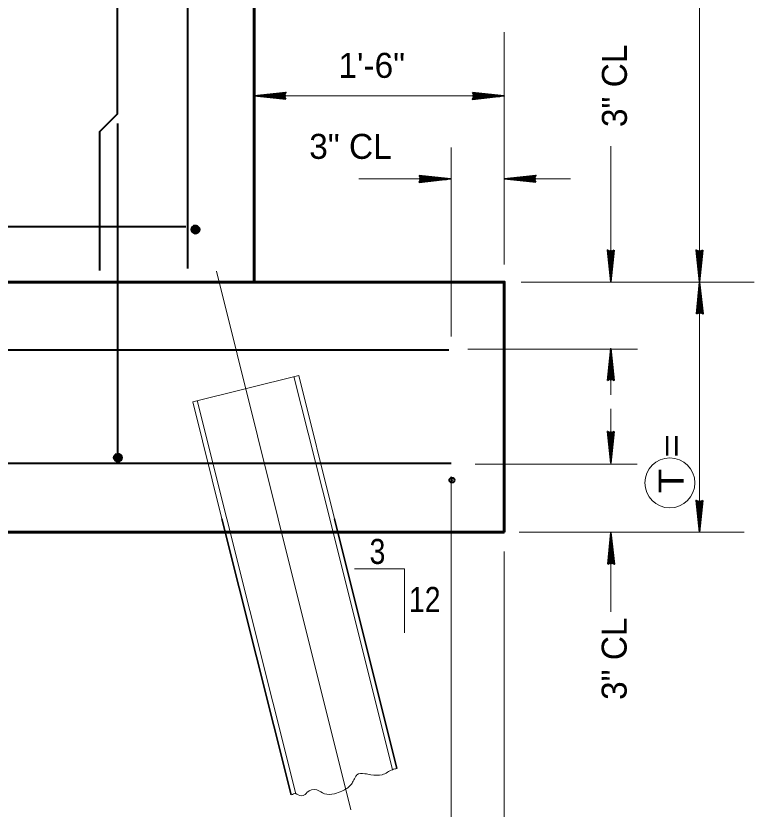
# Model space of a CAD drawing. Extents: x 3.64 to 6.84, y -0.8 to 1.19.
# Drawn here: x 4.5316 to 4.7778, y -0.2344 to 0.03 of the extents above; entities that cross this region are included whole.
import ezdxf
from ezdxf.enums import TextEntityAlignment as Align

# ---------------------------------------------------------------- set-up
doc = ezdxf.new("R2010")
doc.units = 0
doc.header["$LTSCALE"] = 0.0033
doc.header["$PDMODE"] = 32
doc.header["$PDSIZE"] = 0.00165
doc.linetypes.add('DOT_DASHED', pattern=[7.7, 5, -1.2, 0.3, -1.2])
doc.linetypes.add('MEDIUM_DASHED', pattern=[4.5, 3, -1.5])
doc.layers.add('1', color=7, linetype='Continuous', lineweight=40)
doc.layers.add('5', color=7, linetype='MEDIUM_DASHED', lineweight=13)

msp = doc.modelspace()

# ---------------------------------------------------------------- linework, layer by layer
at = {"layer": '1', "lineweight": 13}
for p, q in [((4.759583, 0.27275), (4.759583, -0.142083)), ((4.694417, -0.052833), (4.694417, 0.024583)), ((4.611083, 0.003333), (4.694, 0.003333)), ((4.67675, -0.076833), (4.67675, -0.013917)), ((4.73, -0.04875), (4.73, -0.013417)), ((4.645917, -0.024333), (4.66675, -0.024333)), ((4.704333, -0.024333), (4.7165, -0.024333)), ((4.700083, -0.05875), (4.77775, -0.05875)), ((4.682333, -0.081083), (4.738917, -0.081083)), ((4.729917, -0.096333), (4.729917, -0.086417)), ((4.73, -0.110833), (4.73, -0.101)), ((4.68475, -0.119417), (4.73875, -0.119417)), ((4.67675, -0.123583), (4.67675, -0.36975)), ((4.67675, -0.13175), (4.67675, -0.133333)), ((4.694417, -0.142083), (4.694417, -0.142417)), ((4.699417, -0.142083), (4.774417, -0.142083)), ((4.694417, -0.148583), (4.694417, -0.230333)), ((4.73, -0.168583), (4.73, -0.152083)), ((4.6445, -0.15425), (4.661167, -0.15425)), ((4.661167, -0.15425), (4.661167, -0.175583)), ((4.694417, -0.22875), (4.694417, -0.413667))]:
    msp.add_line(p, q, dxfattribs=at)
at = {"layer": '1'}
for p, q in [((4.588833, 0.253083), (4.588833, -0.05425)), ((4.5655, -0.005917), (4.5655, -0.11825)), ((4.471167, -0.040167), (4.588333, -0.040167)), ((4.590333, -0.041833), (4.592333, -0.042167)), ((4.590417, -0.041333), (4.592417, -0.04175)), ((4.590417, -0.041583), (4.592417, -0.041917)), ((4.590417, -0.041667), (4.592333, -0.042)), ((4.590417, -0.04175), (4.592333, -0.042083)), ((4.590583, -0.040417), (4.5905, -0.041917)), ((4.5905, -0.040917), (4.5925, -0.04125)), ((4.5905, -0.041), (4.5925, -0.041417)), ((4.5905, -0.041083), (4.592417, -0.0415)), ((4.5905, -0.041167), (4.592417, -0.041583)), ((4.590667, -0.040417), (4.590583, -0.041917)), ((4.590583, -0.040417), (4.592583, -0.04075)), ((4.590583, -0.0405), (4.592583, -0.040833)), ((4.590583, -0.040583), (4.592583, -0.041)), ((4.590583, -0.040667), (4.592583, -0.041083)), ((4.590583, -0.040833), (4.5925, -0.041167)), ((4.590667, -0.04025), (4.592583, -0.040583)), ((4.59075, -0.040417), (4.590667, -0.041917)), ((4.590833, -0.040417), (4.59075, -0.041917)), ((4.590917, -0.040417), (4.590833, -0.041917)), ((4.591083, -0.040417), (4.591, -0.041917)), ((4.591167, -0.040417), (4.591083, -0.041917)), ((4.59125, -0.040417), (4.591167, -0.041917)), ((4.591333, -0.040417), (4.59125, -0.041917)), ((4.591417, -0.040417), (4.591333, -0.041917)), ((4.5915, -0.040417), (4.591417, -0.041917)), ((4.591583, -0.040417), (4.5915, -0.041917)), ((4.59175, -0.0405), (4.591583, -0.042)), ((4.591917, -0.0405), (4.59175, -0.042)), ((4.592, -0.0405), (4.591917, -0.042)), ((4.592, -0.0405), (4.591917, -0.042)), ((4.592083, -0.0405), (4.592, -0.042)), ((4.592167, -0.0405), (4.592083, -0.042)), ((4.59225, -0.0405), (4.592167, -0.042)), ((4.592333, -0.0405), (4.59225, -0.042)), ((4.592417, -0.0405), (4.592333, -0.042)), ((4.5925, -0.0405), (4.592417, -0.042)), ((4.592667, -0.0405), (4.592583, -0.042)), ((4.565, -0.116083), (4.564667, -0.118083)), ((4.565083, -0.116167), (4.56475, -0.118083)), ((4.565167, -0.116167), (4.564833, -0.118083)), ((4.56525, -0.116167), (4.564917, -0.118167)), ((4.566417, -0.116333), (4.564917, -0.11625)), ((4.5655, -0.116167), (4.565083, -0.118167)), ((4.565667, -0.11625), (4.56525, -0.118167)), ((4.56575, -0.11625), (4.565333, -0.118167)), ((4.565833, -0.11625), (4.565417, -0.11825)), ((4.565917, -0.11625), (4.565583, -0.11825)), ((4.566333, -0.1175), (4.564833, -0.117333)), ((4.566333, -0.117667), (4.564833, -0.1175)), ((4.566333, -0.11775), (4.564833, -0.117667)), ((4.566333, -0.11775), (4.564833, -0.117667)), ((4.566333, -0.117833), (4.564833, -0.11775)), ((4.566333, -0.117917), (4.564833, -0.117833)), ((4.566333, -0.118), (4.564833, -0.117917)), ((4.566333, -0.118083), (4.564833, -0.118)), ((4.566333, -0.118167), (4.564833, -0.118083)), ((4.566333, -0.11825), (4.564833, -0.118167)), ((4.566333, -0.118417), (4.564833, -0.118333)), ((4.566417, -0.116417), (4.564917, -0.116333)), ((4.566417, -0.1165), (4.564917, -0.116417)), ((4.566417, -0.116583), (4.564917, -0.1165)), ((4.566417, -0.116667), (4.564917, -0.116583)), ((4.566417, -0.116833), (4.564917, -0.11675)), ((4.566417, -0.116917), (4.564917, -0.116833)), ((4.566417, -0.117), (4.564917, -0.116917)), ((4.566417, -0.117083), (4.564917, -0.117)), ((4.566417, -0.117167), (4.564917, -0.117083)), ((4.566417, -0.11725), (4.564917, -0.117167)), ((4.566417, -0.117333), (4.564917, -0.11725)), ((4.566, -0.116333), (4.565667, -0.11825)), ((4.566167, -0.116333), (4.56575, -0.118333)), ((4.56625, -0.116333), (4.565833, -0.118333)), ((4.566333, -0.116333), (4.566, -0.118333)), ((4.566417, -0.116333), (4.566083, -0.118333)), ((4.566583, -0.116417), (4.56625, -0.118333))]:
    msp.add_line(p, q, dxfattribs=at)
at = {"layer": '1', "lineweight": 35}
for p, q in [((4.621667, 0.003333), (4.611083, 0.003333)), ((4.621417, 0.0025), (4.613583, 0.0035)), ((4.621417, 0.0025), (4.613583, 0.003333)), ((4.621417, 0.002333), (4.613583, 0.00325)), ((4.621417, 0.002333), (4.613583, 0.00325)), ((4.621417, 0.002417), (4.613583, 0.00325)), ((4.621417, 0.004417), (4.614083, 0.003583)), ((4.621417, 0.00425), (4.614083, 0.0035)), ((4.621417, 0.004167), (4.614083, 0.003333)), ((4.6215, 0.004), (4.614167, 0.00325)), ((4.683833, 0.003333), (4.694417, 0.003333)), ((4.684, 0.002667), (4.691333, 0.003417)), ((4.684083, 0.004333), (4.691917, 0.003417)), ((4.684083, 0.004333), (4.691917, 0.003417)), ((4.684083, 0.00425), (4.691917, 0.003417)), ((4.684083, 0.004167), (4.691917, 0.003333)), ((4.684083, 0.004167), (4.691917, 0.003167)), ((4.684083, 0.0025), (4.691417, 0.003333)), ((4.684083, 0.002417), (4.691417, 0.003167)), ((4.684083, 0.00225), (4.691417, 0.003083)), ((4.666333, -0.023333), (4.674167, -0.02425)), ((4.666333, -0.023333), (4.674167, -0.02425)), ((4.666333, -0.023417), (4.674167, -0.02425)), ((4.666333, -0.0235), (4.674167, -0.024333)), ((4.666333, -0.0235), (4.674167, -0.0245)), ((4.70475, -0.02325), (4.697417, -0.024083)), ((4.70475, -0.023417), (4.697417, -0.024167)), ((4.70475, -0.0235), (4.697417, -0.024333)), ((4.704833, -0.023667), (4.6975, -0.024417)), ((4.666083, -0.024333), (4.676667, -0.024333)), ((4.66625, -0.025), (4.673583, -0.02425)), ((4.666333, -0.025167), (4.673667, -0.024333)), ((4.666333, -0.02525), (4.673667, -0.0245)), ((4.666333, -0.025417), (4.673667, -0.024583)), ((4.705, -0.024333), (4.694417, -0.024333)), ((4.70475, -0.025167), (4.696917, -0.024167)), ((4.70475, -0.025167), (4.696917, -0.024333)), ((4.70475, -0.025333), (4.696917, -0.024417)), ((4.70475, -0.025333), (4.696917, -0.024417)), ((4.70475, -0.02525), (4.696917, -0.024417)), ((4.728917, -0.048333), (4.72975, -0.055667)), ((4.729083, -0.048333), (4.729833, -0.055667)), ((4.729167, -0.048333), (4.73, -0.055667)), ((4.729333, -0.04825), (4.730083, -0.055583)), ((4.730833, -0.048333), (4.729833, -0.056167)), ((4.73, -0.048083), (4.73, -0.058667)), ((4.730833, -0.048333), (4.73, -0.056167)), ((4.731, -0.048333), (4.730083, -0.056167)), ((4.731, -0.048333), (4.730083, -0.056167)), ((4.730917, -0.048333), (4.730083, -0.056167)), ((4.7585, -0.048333), (4.759333, -0.055667)), ((4.758667, -0.048333), (4.759417, -0.055667)), ((4.75875, -0.048333), (4.759583, -0.055667)), ((4.758917, -0.04825), (4.759667, -0.055583)), ((4.760417, -0.048333), (4.759417, -0.056167)), ((4.759583, -0.048083), (4.759583, -0.058667)), ((4.760417, -0.048333), (4.759583, -0.056167)), ((4.760583, -0.048333), (4.759667, -0.056167)), ((4.760583, -0.048333), (4.759667, -0.056167)), ((4.7605, -0.048333), (4.759667, -0.056167)), ((4.759583, -0.069333), (4.759583, -0.05875)), ((4.758583, -0.069083), (4.7595, -0.06125)), ((4.758583, -0.069083), (4.7595, -0.06125)), ((4.758667, -0.069083), (4.7595, -0.06125)), ((4.75875, -0.069083), (4.759583, -0.06125)), ((4.75875, -0.069083), (4.75975, -0.06125)), ((4.76025, -0.069167), (4.7595, -0.061833)), ((4.760417, -0.069083), (4.759583, -0.06175)), ((4.7605, -0.069083), (4.75975, -0.06175)), ((4.760667, -0.069083), (4.759833, -0.06175)), ((4.729917, -0.0915), (4.729917, -0.080917)), ((4.728917, -0.09125), (4.729833, -0.083417)), ((4.728917, -0.09125), (4.729833, -0.083417)), ((4.729, -0.09125), (4.729833, -0.083417)), ((4.729083, -0.09125), (4.729917, -0.083417)), ((4.729083, -0.09125), (4.730083, -0.083417)), ((4.730583, -0.091333), (4.729833, -0.084)), ((4.73075, -0.09125), (4.729917, -0.083917)), ((4.730833, -0.09125), (4.730083, -0.083917)), ((4.731, -0.09125), (4.730167, -0.083917)), ((4.728917, -0.10875), (4.72975, -0.116083)), ((4.729083, -0.10875), (4.729833, -0.116083)), ((4.729167, -0.10875), (4.73, -0.116083)), ((4.729333, -0.108667), (4.730083, -0.116)), ((4.730833, -0.10875), (4.729833, -0.116583)), ((4.73, -0.1085), (4.73, -0.119083)), ((4.730833, -0.10875), (4.73, -0.116583)), ((4.731, -0.10875), (4.730083, -0.116583)), ((4.731, -0.10875), (4.730083, -0.116583)), ((4.730917, -0.10875), (4.730083, -0.116583)), ((4.7585, -0.13175), (4.759333, -0.139083)), ((4.758667, -0.13175), (4.759417, -0.139083)), ((4.75875, -0.13175), (4.759583, -0.139083)), ((4.758917, -0.131667), (4.759667, -0.139)), ((4.760417, -0.13175), (4.759417, -0.139583)), ((4.759583, -0.1315), (4.759583, -0.142083)), ((4.760417, -0.13175), (4.759583, -0.139583)), ((4.760583, -0.13175), (4.759667, -0.139583)), ((4.760583, -0.13175), (4.759667, -0.139583)), ((4.7605, -0.13175), (4.759667, -0.139583)), ((4.73, -0.15275), (4.73, -0.142167)), ((4.729, -0.1525), (4.729917, -0.144667)), ((4.729, -0.1525), (4.729917, -0.144667)), ((4.729083, -0.1525), (4.729917, -0.144667)), ((4.729167, -0.1525), (4.73, -0.144667)), ((4.729167, -0.1525), (4.730167, -0.144667)), ((4.730667, -0.152583), (4.729917, -0.14525)), ((4.730833, -0.1525), (4.73, -0.145167)), ((4.730917, -0.1525), (4.730167, -0.145167)), ((4.731083, -0.1525), (4.73025, -0.145167))]:
    msp.add_line(p, q, dxfattribs=at)
at = {"layer": '1', "lineweight": 60}
msp.add_line((4.694417, -0.142083), (3.944417, -0.142083), dxfattribs=at)
for points in [[(4.611083, 0.274583), (4.611083, -0.05875), (4.694417, -0.05875), (4.694417, -0.142083)], [(4.02775, -0.05875), (4.270917, -0.05875), (4.611083, -0.05875)]]:
    msp.add_lwpolyline(points, dxfattribs=at)
at = {"layer": '1'}
for points in [[(4.565417, 0.253583), (4.565417, -0.00275), (4.5595, -0.008667), (4.5595, -0.054917)], [(4.590167, -0.04125), (4.59275, -0.040917), (4.590417, -0.040417), (4.59275, -0.0415), (4.590333, -0.041917), (4.592333, -0.04225), (4.592333, -0.040167), (4.591417, -0.0425), (4.591667, -0.039917), (4.590667, -0.04225), (4.591, -0.039917), (4.591833, -0.0425), (4.59025, -0.04075), (4.592667, -0.040583), (4.591, -0.042417), (4.592083, -0.04), (4.590417, -0.040417), (4.590333, -0.041917), (4.591417, -0.0425), (4.592333, -0.04225), (4.59275, -0.0415), (4.592667, -0.040583), (4.592083, -0.04), (4.591417, -0.041083), (4.592583, -0.042), (4.590667, -0.04225), (4.591417, -0.041083), (4.590333, -0.040583), (4.591333, -0.039917), (4.591417, -0.041), (4.59225, -0.04225), (4.59025, -0.041), (4.591583, -0.040667), (4.592333, -0.040167)], [(4.270917, -0.077167), (4.33325, -0.077167), (4.3405, -0.081333), (4.675917, -0.081333)], [(4.271, -0.114917), (4.332583, -0.114917), (4.339833, -0.119083), (4.67675, -0.119083)], [(4.565583, -0.115917), (4.565917, -0.1185), (4.566417, -0.116167), (4.565333, -0.1185), (4.564917, -0.116083), (4.564583, -0.118083), (4.566667, -0.118083), (4.564333, -0.117167), (4.566917, -0.117417), (4.564583, -0.116417), (4.566917, -0.11675), (4.564333, -0.117583), (4.566083, -0.116), (4.56625, -0.118417), (4.564417, -0.11675), (4.566833, -0.117833), (4.566417, -0.116167), (4.564917, -0.116083), (4.564333, -0.117167), (4.564583, -0.118083), (4.565333, -0.1185), (4.56625, -0.118417), (4.566833, -0.117833), (4.56575, -0.117167), (4.564833, -0.118333), (4.564583, -0.116417), (4.56575, -0.117167), (4.56625, -0.116083), (4.566917, -0.117083), (4.565833, -0.117167), (4.564583, -0.118), (4.565833, -0.116), (4.566167, -0.117333), (4.566667, -0.118083)]]:
    msp.add_lwpolyline(points, dxfattribs=at)
at = {"layer": '1', "lineweight": 35}
for points in [[(4.621667, 0.00225), (4.611083, 0.003333), (4.621667, 0.0045), (4.621083, 0.003333)], [(4.620917, 0.00325), (4.61625, 0.003167), (4.61625, 0.00325), (4.617167, 0.00325), (4.620917, 0.003167), (4.617917, 0.003083), (4.621083, 0.003), (4.618833, 0.002917), (4.621083, 0.002833), (4.617583, 0.003083), (4.612917, 0.00325), (4.613833, 0.0035), (4.612583, 0.0035), (4.620917, 0.0035), (4.6185, 0.003667), (4.621083, 0.003667), (4.61575, 0.00325), (4.621083, 0.003917)], [(4.683833, 0.004417), (4.694417, 0.003333), (4.683833, 0.002167), (4.684417, 0.003333)], [(4.684583, 0.003417), (4.68925, 0.0035), (4.68925, 0.003417), (4.688333, 0.003417), (4.684583, 0.0035), (4.687583, 0.003583), (4.684417, 0.003667), (4.686667, 0.00375), (4.684417, 0.003833), (4.687917, 0.003583), (4.692583, 0.003417), (4.691667, 0.003167), (4.692917, 0.003167), (4.684583, 0.003167), (4.687, 0.003), (4.684417, 0.003), (4.68975, 0.003417), (4.684417, 0.00275)], [(4.666083, -0.02325), (4.676667, -0.024333), (4.666083, -0.0255), (4.666667, -0.024333)], [(4.705, -0.025417), (4.694417, -0.024333), (4.705, -0.023167), (4.704417, -0.024333)], [(4.70425, -0.024417), (4.699583, -0.0245), (4.699583, -0.024417), (4.7005, -0.024417), (4.70425, -0.0245), (4.70125, -0.024583), (4.704417, -0.024667), (4.702167, -0.02475), (4.704417, -0.024833), (4.700917, -0.024583), (4.69625, -0.024417), (4.697167, -0.024167), (4.695917, -0.024167), (4.70425, -0.024167), (4.701833, -0.024), (4.704417, -0.024), (4.699083, -0.024417), (4.704417, -0.02375)], [(4.666833, -0.02425), (4.6715, -0.024167), (4.6715, -0.02425), (4.670583, -0.02425), (4.666833, -0.024167), (4.669833, -0.024083), (4.666667, -0.024), (4.668917, -0.023917), (4.666667, -0.023833), (4.670167, -0.024083), (4.674833, -0.02425), (4.673917, -0.0245), (4.675167, -0.0245), (4.666833, -0.0245), (4.66925, -0.024667), (4.666667, -0.024667), (4.672, -0.02425), (4.666667, -0.024917)], [(4.731083, -0.048083), (4.73, -0.058667), (4.728833, -0.048083), (4.73, -0.048667)], [(4.730083, -0.048833), (4.730167, -0.0535), (4.730083, -0.0535), (4.730083, -0.052583), (4.730167, -0.048833), (4.73025, -0.051833), (4.730333, -0.048667), (4.730417, -0.050917), (4.7305, -0.048667), (4.73025, -0.052167), (4.730083, -0.056833), (4.729833, -0.055917), (4.729833, -0.057167), (4.729833, -0.048833), (4.729667, -0.05125), (4.729667, -0.048667), (4.730083, -0.054), (4.729417, -0.048667)], [(4.760667, -0.048083), (4.759583, -0.058667), (4.758417, -0.048083), (4.759583, -0.048667)], [(4.759667, -0.048833), (4.75975, -0.0535), (4.759667, -0.0535), (4.759667, -0.052583), (4.75975, -0.048833), (4.759833, -0.051833), (4.759917, -0.048667), (4.76, -0.050917), (4.760083, -0.048667), (4.759833, -0.052167), (4.759667, -0.056833), (4.759417, -0.055917), (4.759417, -0.057167), (4.759417, -0.048833), (4.75925, -0.05125), (4.75925, -0.048667), (4.759667, -0.054), (4.759, -0.048667)], [(4.7585, -0.069333), (4.759583, -0.05875), (4.76075, -0.069333), (4.759583, -0.06875)], [(4.7595, -0.068583), (4.759417, -0.063917), (4.7595, -0.063917), (4.7595, -0.064833), (4.759417, -0.068583), (4.759333, -0.065583), (4.75925, -0.06875), (4.759167, -0.0665), (4.759083, -0.06875), (4.759333, -0.06525), (4.7595, -0.060583), (4.75975, -0.0615), (4.75975, -0.06025), (4.75975, -0.068583), (4.759917, -0.066167), (4.759917, -0.06875), (4.7595, -0.063417), (4.760167, -0.06875)], [(4.728833, -0.0915), (4.729917, -0.080917), (4.731083, -0.0915), (4.729917, -0.090917)], [(4.729833, -0.09075), (4.72975, -0.086083), (4.729833, -0.086083), (4.729833, -0.087), (4.72975, -0.09075), (4.729667, -0.08775), (4.729583, -0.090917), (4.7295, -0.088667), (4.729417, -0.090917), (4.729667, -0.087417), (4.729833, -0.08275), (4.730083, -0.083667), (4.730083, -0.082417), (4.730083, -0.09075), (4.73025, -0.088333), (4.73025, -0.090917), (4.729833, -0.085583), (4.7305, -0.090917)], [(4.731083, -0.1085), (4.73, -0.119083), (4.728833, -0.1085), (4.73, -0.109083)], [(4.730083, -0.10925), (4.730167, -0.113917), (4.730083, -0.113917), (4.730083, -0.113), (4.730167, -0.10925), (4.73025, -0.11225), (4.730333, -0.109083), (4.730417, -0.111333), (4.7305, -0.109083), (4.73025, -0.112583), (4.730083, -0.11725), (4.729833, -0.116333), (4.729833, -0.117583), (4.729833, -0.10925), (4.729667, -0.111667), (4.729667, -0.109083), (4.730083, -0.114417), (4.729417, -0.109083)], [(4.760667, -0.1315), (4.759583, -0.142083), (4.758417, -0.1315), (4.759583, -0.132083)], [(4.759667, -0.13225), (4.75975, -0.136917), (4.759667, -0.136917), (4.759667, -0.136), (4.75975, -0.13225), (4.759833, -0.13525), (4.759917, -0.132083), (4.76, -0.134333), (4.760083, -0.132083), (4.759833, -0.135583), (4.759667, -0.14025), (4.759417, -0.139333), (4.759417, -0.140583), (4.759417, -0.13225), (4.75925, -0.134667), (4.75925, -0.132083), (4.759667, -0.137417), (4.759, -0.132083)], [(4.728917, -0.15275), (4.73, -0.142167), (4.731167, -0.15275), (4.73, -0.152167)], [(4.729917, -0.152), (4.729833, -0.147333), (4.729917, -0.147333), (4.729917, -0.14825), (4.729833, -0.152), (4.72975, -0.149), (4.729667, -0.152167), (4.729583, -0.149917), (4.7295, -0.152167), (4.72975, -0.148667), (4.729917, -0.144), (4.730167, -0.144917), (4.730167, -0.143667), (4.730167, -0.152), (4.730333, -0.149583), (4.730333, -0.152167), (4.729917, -0.146833), (4.730583, -0.152167)]]:
    msp.add_lwpolyline(points, close=True, dxfattribs=at)
for points in [[(4.620917, 0.00325), (4.621333, 0.0025), (4.621083, 0.00275), (4.620917, 0.003083), (4.620667, 0.003), (4.620833, 0.002667), (4.621, 0.003417), (4.621167, 0.003917), (4.621417, 0.004333)], [(4.684583, 0.003417), (4.684167, 0.004167), (4.684417, 0.003917), (4.684583, 0.003583), (4.684833, 0.003667), (4.684667, 0.004), (4.6845, 0.00325), (4.684333, 0.00275), (4.684083, 0.002333)], [(4.666833, -0.02425), (4.666417, -0.0235), (4.666667, -0.02375), (4.666833, -0.024083), (4.667083, -0.024), (4.666917, -0.023667), (4.66675, -0.024417), (4.666583, -0.024917), (4.666333, -0.025333)], [(4.70425, -0.024417), (4.704667, -0.025167), (4.704417, -0.024917), (4.70425, -0.024583), (4.704, -0.024667), (4.704167, -0.025), (4.704333, -0.02425), (4.7045, -0.02375), (4.70475, -0.023333)], [(4.730083, -0.048833), (4.730833, -0.048417), (4.730583, -0.048667), (4.73025, -0.048833), (4.730333, -0.049083), (4.730667, -0.048917), (4.729917, -0.04875), (4.729417, -0.048583), (4.729, -0.048333)], [(4.759667, -0.048833), (4.760417, -0.048417), (4.760167, -0.048667), (4.759833, -0.048833), (4.759917, -0.049083), (4.76025, -0.048917), (4.7595, -0.04875), (4.759, -0.048583), (4.758583, -0.048333)], [(4.7595, -0.068583), (4.75875, -0.069), (4.759, -0.06875), (4.759333, -0.068583), (4.75925, -0.068333), (4.758917, -0.0685), (4.759667, -0.068667), (4.760167, -0.068833), (4.760583, -0.069083)], [(4.729833, -0.09075), (4.729083, -0.091167), (4.729333, -0.090917), (4.729667, -0.09075), (4.729583, -0.0905), (4.72925, -0.090667), (4.73, -0.090833), (4.7305, -0.091), (4.730917, -0.09125)], [(4.730083, -0.10925), (4.730833, -0.108833), (4.730583, -0.109083), (4.73025, -0.10925), (4.730333, -0.1095), (4.730667, -0.109333), (4.729917, -0.109167), (4.729417, -0.109), (4.729, -0.10875)], [(4.759667, -0.13225), (4.760417, -0.131833), (4.760167, -0.132083), (4.759833, -0.13225), (4.759917, -0.1325), (4.76025, -0.132333), (4.7595, -0.132167), (4.759, -0.132), (4.758583, -0.13175)], [(4.729917, -0.152), (4.729167, -0.152417), (4.729417, -0.152167), (4.72975, -0.152), (4.729667, -0.15175), (4.729333, -0.151917), (4.730083, -0.152083), (4.730583, -0.15225), (4.731, -0.1525)]]:
    msp.add_lwpolyline(points, dxfattribs=at)
at = {"layer": '1'}
for centre in [(4.5915, -0.0412), (4.565633, -0.11725)]:
    msp.add_circle(centre, 0.00132, dxfattribs=at)
at = {"layer": '1', "lineweight": 13}
msp.add_circle((4.749667, -0.125667), 0.008333, dxfattribs=at)
at = {"layer": '1'}
msp.add_point((4.677, -0.12475), dxfattribs=at)
at = {"layer": '5'}
for p, q in [((4.625917, -0.089917), (4.590583, -0.098667)), ((4.624333, -0.09025), (4.63625, -0.137667)), ((4.625917, -0.089917), (4.637833, -0.137667)), ((4.590583, -0.098667), (4.600333, -0.137667)), ((4.592083, -0.09825), (4.601917, -0.137667))]:
    msp.add_line(p, q, dxfattribs=at)
at = {"layer": '5', "linetype": 'Continuous', "lineweight": 35}
for p, q in [((4.600333, -0.137667), (4.623417, -0.229667)), ((4.637833, -0.137667), (4.658667, -0.220833))]:
    msp.add_line(p, q, dxfattribs=at)
at = {"layer": '5', "linetype": 'Continuous'}
for p, q in [((4.601917, -0.137667), (4.624917, -0.22925)), ((4.63625, -0.137667), (4.657167, -0.22125))]:
    msp.add_line(p, q, dxfattribs=at)
at = {"layer": '5', "linetype": 'DOT_DASHED'}
msp.add_lwpolyline([(4.5985, -0.055083), (4.619083, -0.137667), (4.648417, -0.255)], dxfattribs=at)
at = {"layer": '5', "linetype": 'Continuous'}
msp.add_spline([(4.658667, -0.220833), (4.657167, -0.22125), (4.65375, -0.222917), (4.65, -0.222917), (4.647917, -0.222583), (4.645333, -0.222917), (4.645, -0.223417), (4.644083, -0.225083), (4.64325, -0.226333), (4.640333, -0.228417), (4.637833, -0.22925), (4.6345, -0.22925), (4.632, -0.228), (4.628667, -0.228833), (4.627833, -0.229667), (4.62575, -0.229667), (4.624917, -0.22925), (4.623417, -0.229667)], degree=3, dxfattribs=at)

# ---------------------------------------------------------------- texts
at = {"layer": '1'}
for p in [(4.735333, -0.007083), (4.73525, -0.198)]:
    msp.add_text('3" CL', height=0.008334, rotation=90, dxfattribs=at).set_placement(p)
for s, p in [('1\'-6"', (4.639167, 0.009333)), ('3" CL', (4.629417, -0.017667))]:
    msp.add_text(s, height=0.008334, dxfattribs=at).set_placement(p)
at = {"layer": '1', "width": 1.2}
msp.add_text('T =      ', height=0.008334, rotation=90, dxfattribs=at).set_placement((4.75425, -0.129083))
at = {"layer": '1', "width": 0.85}
msp.add_text('3', height=0.008334, dxfattribs=at).set_placement((4.652167, -0.152667), align=Align.CENTER)
msp.add_text('12', height=0.008334, dxfattribs=at).set_placement((4.662667, -0.168667))

doc.saveas('drawing.dxf')
